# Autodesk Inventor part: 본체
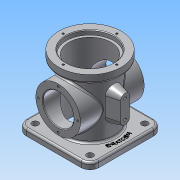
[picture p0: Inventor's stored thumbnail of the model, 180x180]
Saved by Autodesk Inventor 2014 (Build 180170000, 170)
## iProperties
Created: 2021-03
Part Number: 본체
Material: 알루미늄 6061
Document SubType Name: Modeling
Designer: net
Density: 2.71 g/cm^3
Appearance: 알루미늄 - 평지
Mass: 841.498 g
Surface Area: 865.675 cm^2
Volume: 310.516 cm^3
Author: net
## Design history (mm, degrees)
sketch "스케치2"
  geometry: C1 r 38 at (0, 0); 1 further point
  constraints: 1 centre point, 1 coincident
  dimensions: "d3" = 76 diameter of C1
extrude "돌출2" new body sketch "스케치2" stored distance "d4" = 111; taper "d5" = 0 deg
sketch "스케치3"
  geometry: C1 r 38 at (0, 0) reference; C2 r 49 at (0, 0)
  constraints: 1 centre point, 1 coincident
  dimensions: "d6" = 98 diameter of C2
extrude "돌출3" join sketch "스케치3" distance "d7" = 13; taper "d8" = 0 deg
sketch "스케치4"
  geometry: C1 r 49 at (0, 0) reference; C2 r 37 at (0, 0)
  constraints: 1 centre point, 1 coincident
  dimensions: "d9" = 74 diameter of C2
extrude "돌출4" cut sketch "스케치4" distance "d10" = 7; taper "d11" = 0 deg
sketch "스케치5"
  geometry: C1 r 37 at (0, 0) reference; C2 r 33 at (0, 0)
  constraints: 1 centre point, 1 coincident
  dimensions: "d12" = 66 diameter of C2
extrude "돌출5" cut sketch "스케치5" distance "d13" = 104; taper "d14" = 0 deg
sketch "스케치6" dims "d15" = 84
  geometry: C1 r 37 at (0, 0) reference; C2 r 49 at (0, 0) reference; 2 further points
  constraints: 2 vertical alignment, 1 coincident, 2 other
hole "구멍1" sketch "스케치6" at (0, 42) diameter "d16" = 3.242; stored, may be unused: countersink angle "d20" = 90 deg, drill point angle "d22" = 118 deg; dims "d17" = 6, "d18" = 4, "d19" = 2, "d21" = 8
node "작업 평면1"
sketch "스케치7"
  geometry: L1 (-38, -55.5)-(38, -55.5) reference; C1 r 35 at (0, -1.5); 1 further point
  constraints: 1 centre point, 1 vertical alignment
  dimensions: "d27" = 70 diameter of C1; "d96" = 54 vertical distance of L1.start C1.centre
extrude "돌출6" join sketch "스케치7" stored distance "d29" = 7; taper "d30" = 0 deg
sketch "스케치8"
  geometry: C1 r 35 at (0, 0) reference; C2 r 24 at (0, 0); 1 further point
  constraints: 1 centre point, 1 coincident
  dimensions: "d31" = 48 diameter of C2
extrude "돌출7" cut sketch "스케치8" distance "d32" = 50; taper "d33" = 0 deg
sketch "스케치9" dims "d95" = 62
  geometry: C1 r 24 at (0, 0) reference; C2 r 35 at (0, 0) reference; 2 further points
  constraints: 2 vertical alignment, 1 coincident, 2 other
hole "구멍2" sketch "스케치9" at (0, 31) diameter "d35" = 3.242; stored, may be unused: countersink angle "d39" = 90 deg, drill point angle "d41" = 118 deg; dims "d36" = 6, "d37" = 4, "d38" = 2, "d40" = 8
sketch "스케치11"
  geometry: L1 (-57, -57)-(57, -57); L2 (57, -57)-(57, 57); L3 (57, 57)-(-57, 57); L4 (-57, 57)-(-57, -57); L5 (-57, -57)-(57, 57); L6 (57, -57)-(-57, 57); C1 r 38 at (0, 0) reference
  constraints: 12 end point, 2 midpoint, 2 parallel, 1 horizontal, 1 perpendicular
  dimensions: "d48" = 114 distance of L3.end L2.end; "d49" = 114 distance of L2.end L1.end
extrude "돌출8" join sketch "스케치11" distance "d50" = 10; taper "d51" = 0 deg
fillet "모깎기1" dims "d52" = 14
sketch "스케치12"
  geometry: A1 r 14 centre (-43, 43) between (-43, 57) and (-57, 43) reference; A2 r 14 centre (-43, -43) between (-57, -43) and (-43, -57) reference; A3 r 14 centre (43, -43) between (43, -57) and (57, -43) reference; A4 r 14 centre (43, 43) between (57, 43) and (43, 57) reference; 4 further points
  constraints: 4 coincident
hole "구멍3" sketch "스케치12" at (-43, 43), (-43, -43), (43, -43), (43, 43) diameter "d53" = 10; stored, may be unused: countersink angle "d57" = 90 deg, drill point angle "d59" = 118 deg; dims "d54" = 6, "d55" = 4, "d56" = 2, "d58" = 8
fillet "모깎기2" dims "d60" = 3
fillet "모깎기3" dims "d61" = 3
chamfer "모따기1" distance "d62" = 1; stored, may be unused: second distance "d63" = 2, angle "d64" = 45 deg
fillet "모깎기4" dims "d73" = 3
node "작업 평면4"
sketch "스케치14"
  geometry: L1 (0, -12.879)-(0, 16.121); L2 (7, -12.879)-(7, 16.121); L3 (-7, 16.121)-(-7, -12.879); L4 (50.211, -48.5)-(50.211, -55.5) reference; L5 (50.211, -55.5)-(-50.211, -55.5) reference; L6 (-50.211, -55.5)-(-50.211, -48.5) reference; L7 (-43, -45.672)-(43, -45.672) reference; L8 (50.211, -48.5)-(50.211, -55.5) reference; L9 (50.211, -55.5)-(-50.211, -55.5) reference; L10 (-50.211, -55.5)-(-50.211, -48.5) reference; L11 (-43, -45.672)-(43, -45.672) reference; L12 (-50, -36.5)-(-50, 33.5) reference; L13 (50.211, -48.5)-(50.211, -55.5) reference; L14 (50.211, -55.5)-(-50.211, -55.5) reference; L15 (-50.211, -55.5)-(-50.211, -48.5) reference; L16 (-43, -45.672)-(43, -45.672) reference; L17 (50, -36.5)-(50, 33.5) reference; L18 (50, 31.121)-(50, 27.879) reference; L19 (50, 0.121)-(50, -3.121) reference; L20 (50, -30.879)-(50, -34.121) reference; L21 (50, 0.121)-(50, -3.121) reference; L22 (50, -26.5)-(50, 23.5) reference; A1 r 7 centre (0, -12.879) between (-7, -12.879) and (7, -12.879); A2 r 7 centre (0, 16.121) between (7, 16.121) and (-7, 16.121); 4 further points
  constraints: 8 end point, 6 point on circle, 4 tangent, 3 vertical alignment, 2 centre point, 1 midpoint, 1 parallel, 1 vertical, 6 other
  dimensions: "d80" = 43 distance of point (0, -19.879) point (0, 23.121); "d82" = 14 distance between parallel lines of L2 L3; "d97" = 20 vertical distance of L21.start point (0, -19.879)
extrude "돌출10" join sketch "스케치14" stored distance "d83" = 25; taper "d84" = 15 deg
sketch "스케치17"
  geometry: A1 r 7 centre (-16.121, 0) between (-16.121, 7) and (-16.121, -7) reference; A2 r 7 centre (12.879, 0) between (12.879, -7) and (12.879, 7) reference; 3 further points
  constraints: 2 coincident
hole "구멍4" sketch "스케치17" at (12.879, 0), (-16.121, 0) diameter "d85" = 4.134; stored, may be unused: countersink angle "d89" = 90 deg, drill point angle "d91" = 118 deg; dims "d86" = 8, "d87" = 4, "d88" = 2, "d90" = 10
sketch "스케치18"
  geometry: C1 r 41 at (0, 0) reference; C2 r 50 at (0, 0)
  constraints: 1 centre point, 1 coincident, 1 other
  dimensions: "d92" = 100 diameter of C2
feature "엠보싱1" sketch "스케치18" dims "d13" = 104, "d14" = 0, "d93" = 0.5, "d94" = 0
node "솔리드2"
pattern_circular "원형 패턴1" dims angle "d24" = 360 deg
pattern_circular "원형 패턴2" dims angle "d43" = 360 deg
mirror "대칭1"
node "투영된 루프1"
node "절단 모서리 투영3"
node "절단 모서리 투영4"
node "절단 모서리 투영5"
other parameters: "d78" = 55
